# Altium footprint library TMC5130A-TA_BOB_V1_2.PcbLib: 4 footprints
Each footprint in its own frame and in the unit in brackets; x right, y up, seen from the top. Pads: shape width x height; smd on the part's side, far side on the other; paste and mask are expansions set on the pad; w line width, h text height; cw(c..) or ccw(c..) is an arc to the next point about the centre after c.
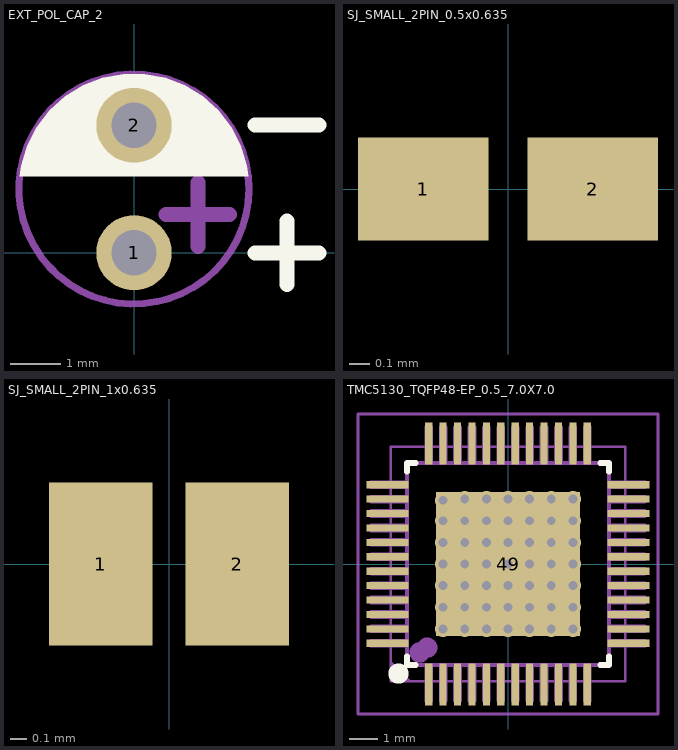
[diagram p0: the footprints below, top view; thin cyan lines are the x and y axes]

## EXT_POL_CAP_2 [mm]
pads (2):
  round 1.5 hole 0.9: 1(0,0) 2(0,2.54)
Top Overlay:
  pour cut-out: 0.889,2.54 0.889,2.628 0.855,2.799 0.788,2.961 0.691,3.107 0.567,3.231 0.421,3.328 0.259,3.395 0.088,3.429 0,3.429 -0.088,3.429 -0.259,3.395 -0.421,3.328 -0.567,3.231 -0.691,3.107 -0.788,2.961 -0.855,2.799 -0.889,2.628 -0.889,2.54 -0.889,2.452 -0.855,2.281 -0.788,2.119 -0.691,1.973 -0.567,1.849 -0.421,1.752 -0.259,1.685 -0.088,1.651 0,1.651 0.088,1.651 0.259,1.685 0.421,1.752 0.567,1.849 0.691,1.973 0.788,2.119 0.855,2.281 0.889,2.452
  region: 0,1.524 -2.272,1.524 -2.249,1.732 -2.128,2.132 -1.936,2.504 -1.68,2.834 -1.368,3.113 -1.011,3.331 -0.62,3.48 -0.209,3.556 0,3.556 0.209,3.556 0.62,3.48 1.011,3.331 1.368,3.113 1.68,2.834 1.936,2.504 2.128,2.132 2.249,1.732 2.272,1.524 0,1.524 0,1.651 0.087,1.655 0.258,1.689 0.419,1.756 0.564,1.853 0.687,1.976 0.784,2.121 0.851,2.282 0.885,2.453 0.889,2.54 0.885,2.627 0.851,2.798 0.784,2.959 0.687,3.104 0.564,3.227 0.419,3.324 0.258,3.391 0.087,3.425 0,3.429 -0.087,3.425 -0.258,3.391 -0.419,3.324 -0.564,3.227 -0.687,3.104 -0.784,2.959 -0.851,2.798 -0.885,2.627 -0.889,2.54 -0.885,2.453 -0.851,2.282 -0.784,2.121 -0.687,1.976 -0.564,1.853 -0.419,1.756 -0.258,1.689 -0.087,1.655 0,1.651
  lines w0.3: 2.413,0 3.683,0 ; 2.413,2.54 3.683,2.54 ; 3.048,-0.635 3.048,0.635
TopAsm:
  circle w0.14: c0,1.27 r2.29
  region: -2.254,1.651 2.258,1.651 2.224,1.849 2.089,2.228 1.89,2.577 1.633,2.886 1.326,3.146 0.978,3.348 0.6,3.486 0.205,3.556 0.004,3.556 -0.198,3.556 -0.594,3.486 -0.972,3.348 -1.32,3.146 -1.627,2.887 -1.885,2.578 -2.085,2.228 -2.22,1.849
  lines w0.3: 0.635,0.762 1.905,0.762 ; 1.27,0.127 1.27,1.397
  text ".Designator" at -1.905,0.762 h1.27

## SJ_SMALL_2PIN_0.5x0.635 [mm]
pads (2):
  rect 0.635x0.5 smd: 1(-0.413,0) 2(0.413,0)

## SJ_SMALL_2PIN_1x0.635 [mm]
pads (2):
  rect 0.635x1 smd: 1(-0.419,0) 2(0.419,0)

## TMC5130_TQFP48-EP_0.5_7.0X7.0 [mm]
pads (49):
  rect 0.25x1.45 smd: 1(-2.75,-4.175) 2(-2.25,-4.175) 3(-1.75,-4.175) 4(-1.25,-4.175) 5(-0.75,-4.175) 6(-0.25,-4.175) 7(0.25,-4.175) 8(0.75,-4.175) 9(1.25,-4.175) 10(1.75,-4.175) 11(2.25,-4.175) 12(2.75,-4.175) 25(2.75,4.175) 26(2.25,4.175) 27(1.75,4.175) 28(1.25,4.175) 29(0.75,4.175) 30(0.25,4.175) 31(-0.25,4.175) 32(-0.75,4.175) 33(-1.25,4.175) 34(-1.75,4.175) 35(-2.25,4.175) 36(-2.75,4.175)
  rect 1.45x0.25 smd: 13(4.175,-2.75) 14(4.175,-2.25) 15(4.175,-1.75) 16(4.175,-1.25) 17(4.175,-0.75) 18(4.175,-0.25) 19(4.175,0.25) 20(4.175,0.75) 21(4.175,1.25) 22(4.175,1.75) 23(4.175,2.25) 24(4.175,2.75) 37(-4.175,2.75) 38(-4.175,2.25) 39(-4.175,1.75) 40(-4.175,1.25) 41(-4.175,0.75) 42(-4.175,0.25) 43(-4.175,-0.25) 44(-4.175,-0.75) 45(-4.175,-1.25) 46(-4.175,-1.75) 47(-4.175,-2.25) 48(-4.175,-2.75)
  rrect0% 5x5 smd paste-254: 49(0,0)
via 0,-1.5 diameter 0.559 hole 0.305
via -0.75,-1.5 diameter 0.559 hole 0.305
via -1.5,-1.5 diameter 0.559 hole 0.305
via -2.25,-1.5 diameter 0.559 hole 0.305
via 0.75,-1.5 diameter 0.559 hole 0.305
via 1.5,-1.5 diameter 0.559 hole 0.305
via 2.25,-1.5 diameter 0.559 hole 0.305
via 0,-0.75 diameter 0.559 hole 0.305
via -0.75,-0.75 diameter 0.559 hole 0.305
via -1.5,-0.75 diameter 0.559 hole 0.305
via -2.25,-0.75 diameter 0.559 hole 0.305
via 0.75,-0.75 diameter 0.559 hole 0.305
via 1.5,-0.75 diameter 0.559 hole 0.305
via 2.25,-0.75 diameter 0.559 hole 0.305
via 0,2.25 diameter 0.559 hole 0.305
via -0.75,2.25 diameter 0.559 hole 0.305
via -1.5,2.25 diameter 0.559 hole 0.305
via 0.75,2.25 diameter 0.559 hole 0.305
via 1.5,2.25 diameter 0.559 hole 0.305
via 2.25,2.25 diameter 0.559 hole 0.305
via 0,1.5 diameter 0.559 hole 0.305
via -0.75,1.5 diameter 0.559 hole 0.305
via -1.5,1.5 diameter 0.559 hole 0.305
via -2.25,1.5 diameter 0.559 hole 0.305
via 0.75,1.5 diameter 0.559 hole 0.305
via 1.5,1.5 diameter 0.559 hole 0.305
via 2.25,1.5 diameter 0.559 hole 0.305
via 0,0.75 diameter 0.559 hole 0.305
via -0.75,0.75 diameter 0.559 hole 0.305
via -1.5,0.75 diameter 0.559 hole 0.305
via -2.25,0.75 diameter 0.559 hole 0.305
via 0.75,0.75 diameter 0.559 hole 0.305
via 1.5,0.75 diameter 0.559 hole 0.305
via 2.25,0.75 diameter 0.559 hole 0.305
via 2.25,0 diameter 0.559 hole 0.305
via 1.5,0 diameter 0.559 hole 0.305
via 0.75,0 diameter 0.559 hole 0.305
via -2.25,0 diameter 0.559 hole 0.305
via -1.5,0 diameter 0.559 hole 0.305
via -0.75,0 diameter 0.559 hole 0.305
via 0,0 diameter 0.559 hole 0.305
via 0,-2.25 diameter 0.559 hole 0.305
via 0.75,-2.25 diameter 0.559 hole 0.305
via 2.25,-2.25 diameter 0.559 hole 0.305
via 1.5,-2.25 diameter 0.559 hole 0.305
via -1.5,-2.25 diameter 0.559 hole 0.305
via -0.75,-2.25 diameter 0.559 hole 0.305
via -2.25,-2.25 diameter 0.559 hole 0.305
via -2.256,2.207 diameter 0.559 hole 0.305
Top Overlay:
  circle w0.5: c-3.8,-3.8 r0.1
  lines w0.2: -3.5,-3.2 -3.5,-3.5 -3.2,-3.5 ; -3.5,3.2 -3.5,3.5 -3.2,3.5 ; 3.2,-3.5 3.5,-3.5 3.5,-3.2 ; 3.2,3.5 3.5,3.5 3.5,3.2
Top Paste:
  region: -2.4,2.4 -0.4,2.4 -0.4,0.4 -2.4,0.4
  region: -2.4,-0.4 -0.4,-0.4 -0.4,-2.4 -2.4,-2.4
  region: 0.4,-0.4 2.4,-0.4 2.4,-2.4 0.4,-2.4
  region: 0.4,2.4 2.4,2.4 2.4,0.4 0.4,0.4
Bottom Solder:
  region: -2.54,2.54 -2.54,-2.54 2.54,-2.54 2.54,2.54
Mechanical 13:
  drawing of 197 lines, arcs and shapes, not listed
Mechanical 15:
  lines w0.1: -5.2,-5.2 5.2,-5.2 5.2,5.2 -5.2,5.2 -5.2,-5.2
TopAsm:
  circle w0.5: c-3.064,-3.064 r0.1
  region: -4.064,-3.358 -3.358,-4.064 -4.064,-4.064
  lines w0.076: -4.064,-4.064 4.064,-4.064 4.064,4.064 -4.064,4.064 -4.064,-4.064
  text ".Designator" at -3.302,-0.508 h1.27
3D body: height 1, standoff 0.05, extent -3.5,-3.5 3.5,3.5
